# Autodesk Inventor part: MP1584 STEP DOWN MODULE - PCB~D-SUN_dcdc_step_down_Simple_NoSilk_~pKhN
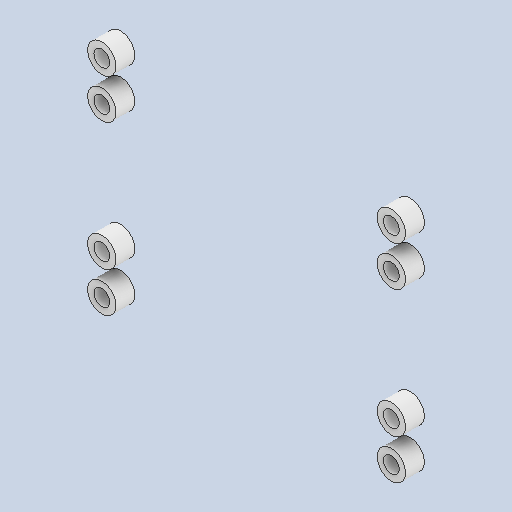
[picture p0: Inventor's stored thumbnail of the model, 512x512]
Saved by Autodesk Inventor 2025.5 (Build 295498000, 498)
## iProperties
Created: 2026-10
Part Number: MP1584 STEP DOWN MODULE - PCB~D-SUN_dcdc_step_down_Simple_NoSilk_~pKhN
Material: Genérico
Document SubType Name: Modeling
Designer: Luis M
Density: 1 g/cm^3
Appearance: Valor por defecto
Author: Luis M
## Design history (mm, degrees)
feature "Base1"
feature "Base2"
feature "Base3"
feature "Base4"
feature "Base5"
feature "Base6"
feature "Base7"
feature "Base8"
node "Sólido1"
node "Sólido2"
node "Sólido3"
node "Sólido4"
node "Sólido5"
node "Sólido6"
node "Sólido7"
node "Sólido8"
